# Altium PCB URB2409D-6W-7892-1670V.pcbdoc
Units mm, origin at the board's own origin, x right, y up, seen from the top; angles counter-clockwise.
Board outline 80 x 45 mm, 2 copper layers (Top Layer, Bottom Layer), stack 0.78 mm thick; 36 components, 14 nets, 82 pads, 146 vias.
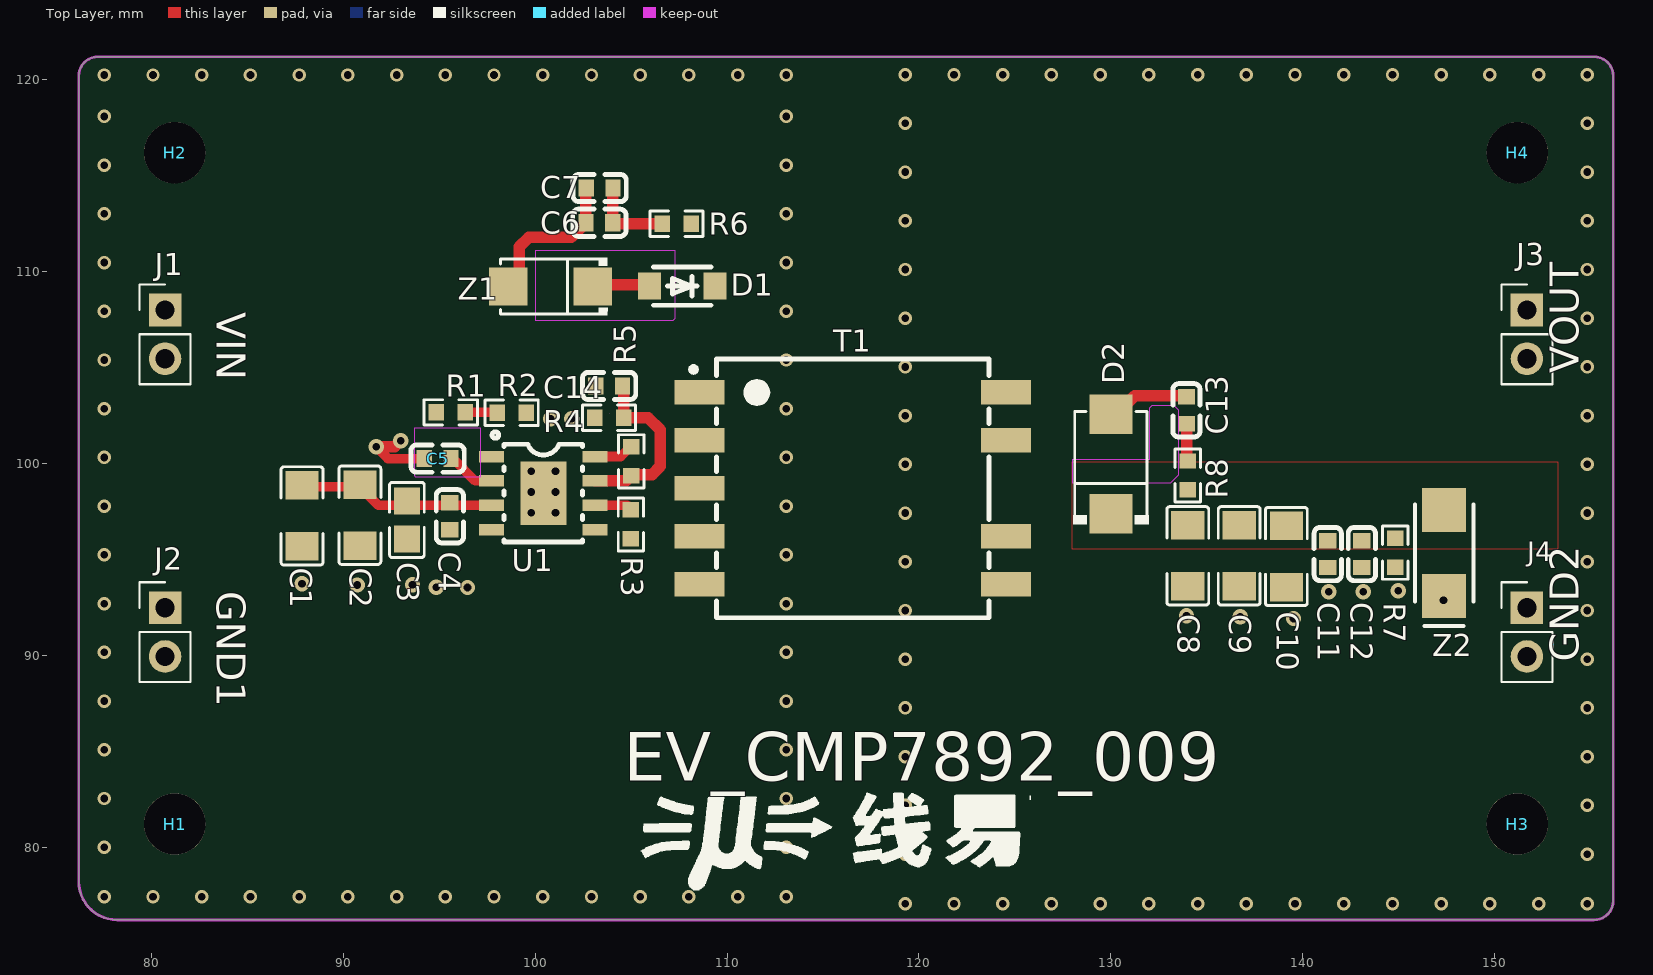
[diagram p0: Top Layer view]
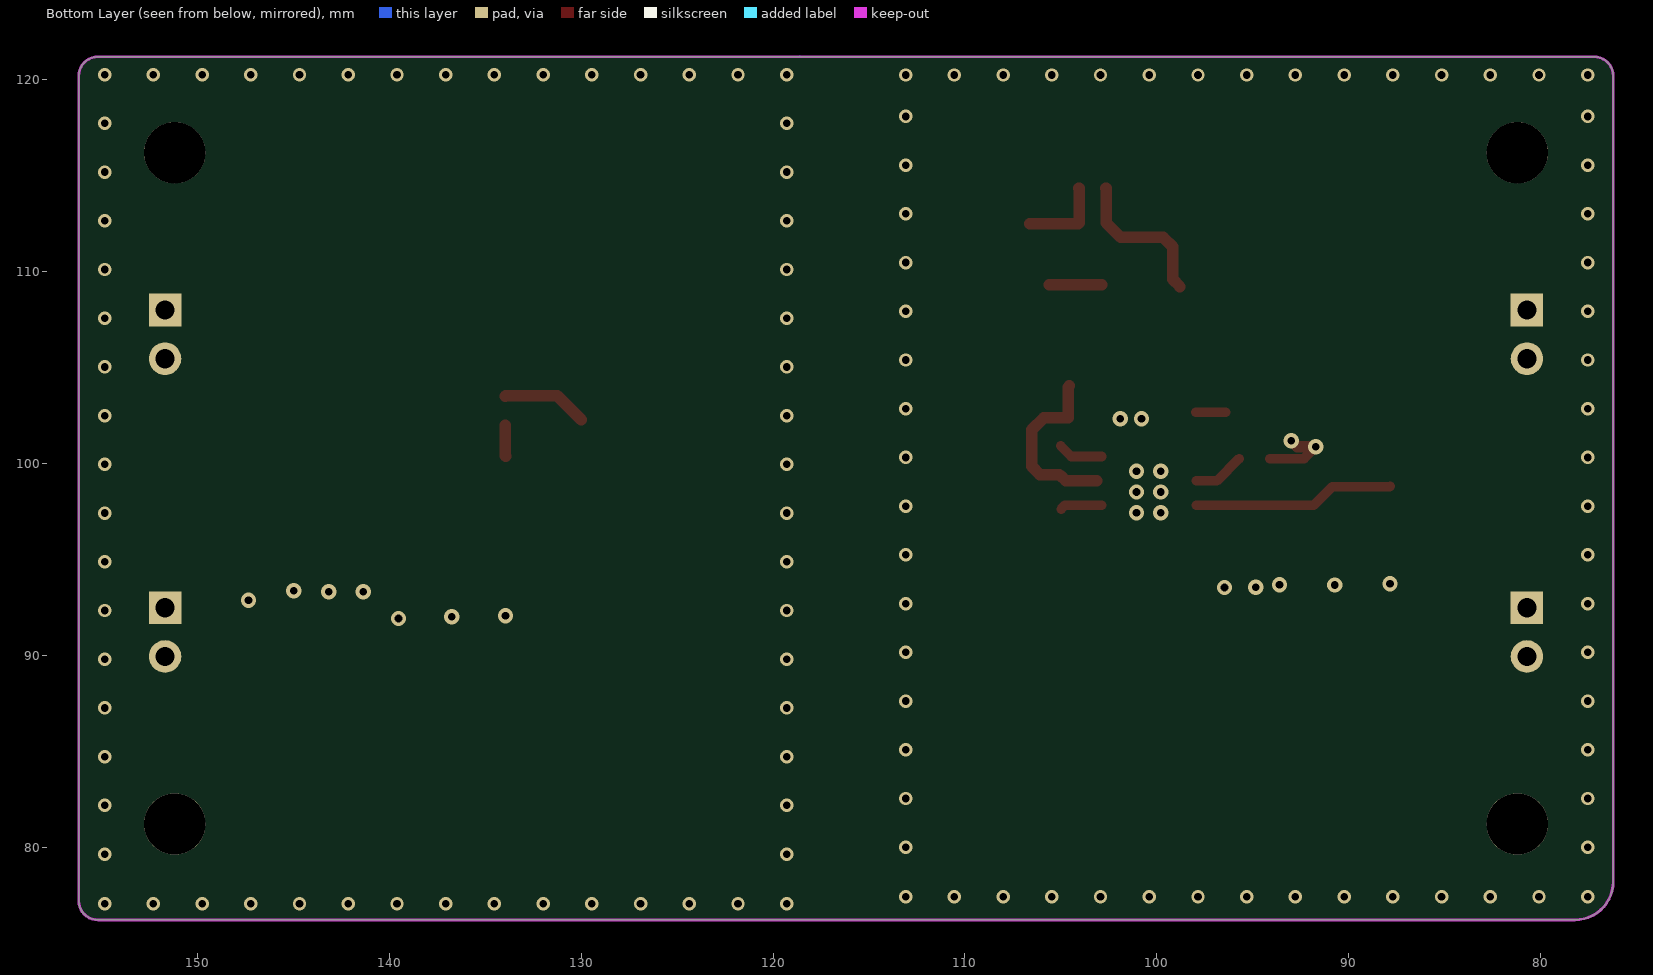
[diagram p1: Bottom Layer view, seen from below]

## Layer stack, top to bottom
Top Solder Mask Layer: solder mask 0.01, Dk 3.3
Top Layer: signal copper 0.035
Dielectric1: surface 0.71, FR4, Dk 4.5
Bottom Layer: signal copper 0.035
Bottom Solder Mask Layer: solder mask 0.01, Dk 3.3

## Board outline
76.2,120.2 cw(c77.2,120.2) 77.2,121.2 155.2,121.2 cw(c155.2,120.2) 156.2,120.2 156.2,77.2 cw(c155.2,77.2) 155.2,76.2 78.2,76.2 cw(c78.2,78.2) 76.2,78.2

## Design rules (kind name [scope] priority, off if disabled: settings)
BoardOutlineClearance safeClearance [All] p0: genericclearance=0.254 ignorepadtopadclearanceinfootprint=FALSE except(0: Arc-SplitContinuation Track-SplitContinuation SMDPad-SplitContinuation THPad-SplitContinuation Via-SplitContinuation Fill-SplitContinuation Poly-SplitContinuation Region-SplitContinuation Text-SplitContinuation)
BoardOutlineClearance Plane_innerPlane [All] p0: genericclearance=0.254 ignorepadtopadclearanceinfootprint=FALSE except(0: Arc-SplitContinuation Track-SplitContinuation SMDPad-SplitContinuation THPad-SplitContinuation Via-SplitContinuation Fill-SplitContinuation Poly-SplitContinuation Region-SplitContinuation Text-SplitContinuation)
BoardOutlineClearance Copper_CopperRegion [All] p0: genericclearance=0.254 ignorepadtopadclearanceinfootprint=FALSE except(0: Arc-SplitContinuation Track-SplitContinuation SMDPad-SplitContinuation THPad-SplitContinuation Via-SplitContinuation Fill-SplitContinuation Poly-SplitContinuation Region-SplitContinuation Text-SplitContinuation)
BoardOutlineClearance Copper_CopperRegion1 [All] p0: genericclearance=0.254 ignorepadtopadclearanceinfootprint=FALSE except(0: Arc-SplitContinuation Track-SplitContinuation SMDPad-SplitContinuation THPad-SplitContinuation Via-SplitContinuation Fill-SplitContinuation Poly-SplitContinuation Region-SplitContinuation Text-SplitContinuation)
BoardOutlineClearance Copper_CopperRegion2 [All] p0: genericclearance=0.254 ignorepadtopadclearanceinfootprint=FALSE except(0: Arc-SplitContinuation Track-SplitContinuation SMDPad-SplitContinuation THPad-SplitContinuation Via-SplitContinuation Fill-SplitContinuation Poly-SplitContinuation Region-SplitContinuation Text-SplitContinuation)
BoardOutlineClearance Copper_CopperRegion3 [All] p0: genericclearance=0.254 ignorepadtopadclearanceinfootprint=FALSE except(0: Arc-SplitContinuation Track-SplitContinuation SMDPad-SplitContinuation THPad-SplitContinuation Via-SplitContinuation Fill-SplitContinuation Poly-SplitContinuation Region-SplitContinuation Text-SplitContinuation)
BoardOutlineClearance Copper_CopperRegion4 [All] p0: genericclearance=0.254 ignorepadtopadclearanceinfootprint=FALSE except(0: Arc-SplitContinuation Track-SplitContinuation SMDPad-SplitContinuation THPad-SplitContinuation Via-SplitContinuation Fill-SplitContinuation Poly-SplitContinuation Region-SplitContinuation Text-SplitContinuation)
BoardOutlineClearance Copper_CopperRegion5 [All] p0: genericclearance=0.254 ignorepadtopadclearanceinfootprint=FALSE except(0: Arc-SplitContinuation Track-SplitContinuation SMDPad-SplitContinuation THPad-SplitContinuation Via-SplitContinuation Fill-SplitContinuation Poly-SplitContinuation Region-SplitContinuation Text-SplitContinuation)
BoardOutlineClearance Copper_CopperRegion6 [All] p0: genericclearance=0.254 ignorepadtopadclearanceinfootprint=FALSE except(0: Arc-SplitContinuation Track-SplitContinuation SMDPad-SplitContinuation THPad-SplitContinuation Via-SplitContinuation Fill-SplitContinuation Poly-SplitContinuation Region-SplitContinuation Text-SplitContinuation)
BoardOutlineClearance Copper_CopperRegion7 [All] p0: genericclearance=0.254 ignorepadtopadclearanceinfootprint=FALSE except(0: Arc-SplitContinuation Track-SplitContinuation SMDPad-SplitContinuation THPad-SplitContinuation Via-SplitContinuation Fill-SplitContinuation Poly-SplitContinuation Region-SplitContinuation Text-SplitContinuation)
BoardOutlineClearance Copper_CopperRegion8 [All] p0: genericclearance=0.254 ignorepadtopadclearanceinfootprint=FALSE except(0: Arc-SplitContinuation Track-SplitContinuation SMDPad-SplitContinuation THPad-SplitContinuation Via-SplitContinuation Fill-SplitContinuation Poly-SplitContinuation Region-SplitContinuation Text-SplitContinuation)
BoardOutlineClearance Copper_CopperRegion9 [All] p0: genericclearance=0.254 ignorepadtopadclearanceinfootprint=FALSE except(0: Arc-SplitContinuation Track-SplitContinuation SMDPad-SplitContinuation THPad-SplitContinuation Via-SplitContinuation Fill-SplitContinuation Poly-SplitContinuation Region-SplitContinuation Text-SplitContinuation)
BoardOutlineClearance Copper_CopperRegion10 [All] p0: genericclearance=0.254 ignorepadtopadclearanceinfootprint=FALSE except(0: Arc-SplitContinuation Track-SplitContinuation SMDPad-SplitContinuation THPad-SplitContinuation Via-SplitContinuation Fill-SplitContinuation Poly-SplitContinuation Region-SplitContinuation Text-SplitContinuation)
BoardOutlineClearance Copper_CopperRegion11 [All] p0: genericclearance=0.254 ignorepadtopadclearanceinfootprint=FALSE except(0: Arc-SplitContinuation Track-SplitContinuation SMDPad-SplitContinuation THPad-SplitContinuation Via-SplitContinuation Fill-SplitContinuation Poly-SplitContinuation Region-SplitContinuation Text-SplitContinuation)
BoardOutlineClearance otherClearance [All] p0: genericclearance=0.254 ignorepadtopadclearanceinfootprint=FALSE except(0: Arc-SplitContinuation Track-SplitContinuation SMDPad-SplitContinuation THPad-SplitContinuation Via-SplitContinuation Fill-SplitContinuation Poly-SplitContinuation Region-SplitContinuation Text-SplitContinuation)
Clearance safeClearance [All] p1: gap=0.178 ignorepadtopadclearanceinfootprint=FALSE
Clearance Plane_innerPlane [All] p1: gap=0.178 ignorepadtopadclearanceinfootprint=FALSE
Clearance Copper_CopperRegion [All] p1: gap=0.178 ignorepadtopadclearanceinfootprint=FALSE
Clearance Copper_CopperRegion1 [All] p1: gap=0.178 ignorepadtopadclearanceinfootprint=FALSE
Clearance Copper_CopperRegion2 [All] p1: gap=0.178 ignorepadtopadclearanceinfootprint=FALSE
Clearance Copper_CopperRegion3 [All] p1: gap=0.178 ignorepadtopadclearanceinfootprint=FALSE
Clearance Copper_CopperRegion4 [All] p1: gap=0.178 ignorepadtopadclearanceinfootprint=FALSE
Clearance Copper_CopperRegion5 [All] p1: gap=0.178 ignorepadtopadclearanceinfootprint=FALSE
Clearance Copper_CopperRegion6 [All] p1: gap=0.178 ignorepadtopadclearanceinfootprint=FALSE
Clearance Copper_CopperRegion7 [All] p1: gap=0.178 ignorepadtopadclearanceinfootprint=FALSE
Clearance Copper_CopperRegion8 [All] p1: gap=0.178 ignorepadtopadclearanceinfootprint=FALSE
Clearance Copper_CopperRegion9 [All] p1: gap=0.178 ignorepadtopadclearanceinfootprint=FALSE
Clearance Copper_CopperRegion10 [All] p1: gap=0.178 ignorepadtopadclearanceinfootprint=FALSE
Clearance Copper_CopperRegion11 [All] p1: gap=0.178 ignorepadtopadclearanceinfootprint=FALSE
Clearance otherClearance [All] p1: gap=0.178 ignorepadtopadclearanceinfootprint=FALSE
DiffPairsRouting differentialPair [All] p1: maxuncoupledlength=10 minlimit=6 maxlimit=Infinity mostfreqgap=6 toplayer_minwidth=5 toplayer_prefwidth=10 toplayer_maxwidth=100 bottomlayer_minwidth=5 bottomlayer_prefwidth=10 bottomlayer_maxwidth=100
PasteMaskExpansion Common [All] p1: expansion=0
PlaneConnect innerPlane [All] p1: planeconnectstyle=Relief reliefexpansion=0.508 reliefentries=4 reliefconductorwidth=0.254 reliefairgap=0.254
PolygonConnect CopperRegion [All] p1: connectstyle=Direct reliefentries=4 reliefconductorwidth=10 polygonreliefangle="90 Angle" airgapwidth=10
PolygonConnect CopperRegion1 [All] p1: connectstyle=Direct reliefentries=4 reliefconductorwidth=10 polygonreliefangle="90 Angle" airgapwidth=10
PolygonConnect CopperRegion2 [All] p1: connectstyle=Direct reliefentries=4 reliefconductorwidth=10 polygonreliefangle="90 Angle" airgapwidth=10
PolygonConnect CopperRegion3 [All] p1: connectstyle=Direct reliefentries=4 reliefconductorwidth=10 polygonreliefangle="90 Angle" airgapwidth=10
PolygonConnect CopperRegion4 [All] p1: connectstyle=Relief reliefentries=4 reliefconductorwidth=0 polygonreliefangle="90 Angle" airgapwidth=1
PolygonConnect CopperRegion5 [All] p1: connectstyle=Relief reliefentries=4 reliefconductorwidth=0 polygonreliefangle="90 Angle" airgapwidth=1
PolygonConnect CopperRegion6 [All] p1: connectstyle=Direct reliefentries=4 reliefconductorwidth=10 polygonreliefangle="90 Angle" airgapwidth=10
PolygonConnect CopperRegion7 [All] p1: connectstyle=Direct reliefentries=4 reliefconductorwidth=10 polygonreliefangle="90 Angle" airgapwidth=10
PolygonConnect CopperRegion8 [All] p1: connectstyle=Direct reliefentries=4 reliefconductorwidth=10 polygonreliefangle="90 Angle" airgapwidth=10
PolygonConnect CopperRegion9 [All] p1: connectstyle=Direct reliefentries=4 reliefconductorwidth=10 polygonreliefangle="90 Angle" airgapwidth=10
PolygonConnect CopperRegion10 [All] p1: connectstyle=Relief reliefentries=4 reliefconductorwidth=0 polygonreliefangle="90 Angle" airgapwidth=1
PolygonConnect CopperRegion11 [All] p1: connectstyle=Relief reliefentries=4 reliefconductorwidth=0 polygonreliefangle="90 Angle" airgapwidth=1
RoutingVias viaSize [All] p1: viastyle="Through Hole" holewidth=12 minholewidth=11.8 maxholewidth=236.2 width=12 minwidth=11.8 maxwidth=236.2
SolderMaskExpansion Common [All] p1: useseparateexpansions=TRUE expansion=0 expansionbottom=0
Width trackWidth [All] p1: maxlimit=100 minlimit=5 preferedwidth=10

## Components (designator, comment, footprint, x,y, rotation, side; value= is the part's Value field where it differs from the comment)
C1 "" C1206 87.841,97.261 r270 top
C2 "" C1206 90.855,97.3 r270 top
C3 "" C0805#1 93.309,97.051 r270 top
C4 "" C0603 95.545,97.24 r90 top
C5 "" C0603 94.905,100.25 r0 top
C6 "" C0603 103.342,112.545 r0 top
C7 "" C0603 103.356,114.357 r0 top
C8 "" C1206 134.02,95.18 r270 top
C9 "" C1206 136.7,95.18 r270 top
C10 "" C1206 139.156,95.146 r90 top
C11 "" C0805#2 141.315,95.273 r90 top
C12 "" C0603 143.093,95.273 r90 top
C13 "" C0603 133.949,102.766 r90 top
C14 "" C0603 103.85,104.036 r0 top
D1 "" SOD-123_L2.8-W1.8-LS3.7-FD 107.66,109.243 r0 top
D2 "" SMB_L4.6-W3.5-LS5.3-RD 130.012,99.972 r90 top
H1 "Mechanical_MountingHole" MountingHole:MountingHole_3.2mm_M3_DIN965 81.2,81.2 r0 top
H2 "" MountingHole:MountingHole_3.2mm_M3_DIN965 81.2,116.2 r0 top
H3 "" MountingHole:MountingHole_3.2mm_M3_DIN965 151.2,81.2 r0 top
H4 "" MountingHole:MountingHole_3.2mm_M3_DIN965 151.2,116.2 r0 top
J1 "" Connector_PinHeader_2.54mm:PinHeader_1x02_P2.54mm_Vertical 80.7,108 r0 top
J2 "" Connector_PinHeader_2.54mm:PinHeader_1x02_P2.54mm_Vertical 80.7,92.475 r0 top
J3 "" Connector_PinHeader_2.54mm:PinHeader_1x02_P2.54mm_Vertical 151.7,108 r0 top
J4 "Connector_Generic_Conn_01x02" Connector_PinHeader_2.54mm:PinHeader_1x02_P2.54mm_Vertical 151.7,92.475 r0 top
R1 "" R0603 95.595,102.658 r0 top
R2 "" R0603 98.77,102.639 r0 top
R3 "" R0603 104.985,96.82 r270 top
R4 "" R0603 103.85,102.385 r180 top
R5 "" MYLibrary:R0603 105.005,100.11 r270 top
R6 "" R1206 107.37,112.49 r180 top
R7 "" R0603 144.833,95.347 r90 top
R8 "" MYLibrary:R0603 134.012,99.371 r90 top
T1 "" XFMR-SMD_CMB1670V 116.55,98.702 r0 top
U1 "" ? 100.421,98.448 r0 top
Z1 "" SMA_L4.3-W2.6-LS5.2-RD 100.787,109.22 r180 top
Z2 "" Diode_SMD:D_SMA 147.383,95.327 r270 top

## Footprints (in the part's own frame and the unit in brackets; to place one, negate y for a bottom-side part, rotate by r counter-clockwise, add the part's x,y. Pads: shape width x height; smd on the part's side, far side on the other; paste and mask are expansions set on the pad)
C0603 [mm]
  rect 0.8x0.9 smd: 1(-0.7,0) 2(0.7,0)
  silkscreen extent -1.39,-0.71 1.39,0.71
C0805#1 [mm]
  rect 1.41x1.35 smd: 1(-1,0) 2(1,0)
  silkscreen extent -1.96,-0.9 1.96,0.9
C0805#2 [mm]
  rect 0.8x0.9 smd: 1(-0.7,0) 2(0.7,0)
  silkscreen extent -1.39,-0.71 1.39,0.71
C1206 [mm]
  rect 1.485x1.728 smd: 1(-1.593,0) 2(1.593,0)
  silkscreen extent -2.56,-1.09 2.56,1.09
Connector_PinHeader_2.54mm:PinHeader_1x02_P2.54mm_Vertical [mm]
  rect 1.7x1.7 hole 1: 1(0,0)
  round 1.7 hole 1: 2(0,-2.54)
  silkscreen extent -1.33,-3.87 1.33,1.33
Diode_SMD:D_SMA [mm]
  rect 2.3x2.3 smd: 1(-2.25,0) 2(2.25,0)
  silkscreen extent -2.54,-1.52 3.81,1.52
MountingHole:MountingHole_3.2mm_M3_DIN965 [mm]
  round 3.2 hole 3.2 unplated: ""(0,0)
MYLibrary:R0603 [mm]
  rect 0.806x0.864 smd: 1(-0.753,0) 2(0.753,0)
  silkscreen extent -1.39,-0.66 1.39,0.66
R0603 [mm]
  rect 0.806x0.864 smd: 1(-0.753,0) 2(0.753,0)
  silkscreen extent -1.39,-0.66 1.39,0.66
R1206 [mm]
  rect 0.806x0.864 smd: 1(-0.753,0) 2(0.753,0)
  silkscreen extent -1.39,-0.66 1.39,0.66
SMA_L4.3-W2.6-LS5.2-RD [mm]
  rect 2x2 smd: 1(-2.2,0) 2(2.2,0)
  silkscreen extent -2.98,-1.5 2.6,1.5
SMB_L4.6-W3.5-LS5.3-RD [mm]
  rect 2.047x2.241 smd: 1(-2.591,0) 2(2.591,0)
  silkscreen extent -3.13,-1.96 2.73,1.96
SOD-123_L2.8-W1.8-LS3.7-FD [mm]
  rect 1.2x1.4 smd: 1(-1.7,0) 2(1.7,0)
  silkscreen extent -1.5,-1 1.5,1
XFMR-SMD_CMB1670V [mm]
  rect 2.62x1.27 smd: 1(-7.99,5) 2(-7.99,2.5) 3(-7.99,0) 4(-7.99,-2.5) 5(-7.99,-5) 6(7.99,-5) 7(7.99,-2.5) 9(7.99,2.5) 10(7.99,5)
  silkscreen extent -8.57,-6.75 7.1,6.75
? [mm]
  rect 1.3x0.6 smd: 1(-2.7,1.905) 2(-2.7,0.635) 3(-2.7,-0.635) 4(-2.7,-1.905) 5(2.7,-1.905) 6(2.7,-0.635) 7(2.7,0.635) 8(2.7,1.905)
  rect 2.4x3.3 smd: 9(0,0)
  silkscreen extent -2.67,-2.55 2.05,3.2

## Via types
v1: diameter 0.7, hole 0.4, Top Layer to Bottom Layer, 124 vias
v2: diameter 0.8, hole 0.4, Top Layer to Bottom Layer, 22 vias

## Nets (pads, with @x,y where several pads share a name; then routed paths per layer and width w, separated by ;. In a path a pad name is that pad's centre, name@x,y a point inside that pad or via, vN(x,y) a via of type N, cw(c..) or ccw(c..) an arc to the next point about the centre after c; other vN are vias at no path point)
$1N7: C13.1 R8.2 | length 1.6
  Top Layer w0.6: R8.2@133.95,100.37 133.97,100.39 C13.1@133.97,101.99
$1N594: D1.1 Z1.1 | length 2.8
  Top Layer w0.25: Z1.1@102.788,109.22 Z1.1@102.878,109.31
  Top Layer w0.6: Z1.1@102.878,109.31 D1.1@105.6,109.31
$1N2001: C5.2 U1.2 | length 2.7
  Top Layer w0.5: C5.2@95.705,100.25 96.865,99.09 U1.2@97.925,99.09
$1N2197: C6.2 C7.2 R6.2 | length 4.3
  Top Layer w0.599: C6.2 104.042,114.344 C7.2
  Top Layer w0.6: C6.2@104.104,112.49 R6.2
$1N9856: C13.2 D2.2 T1.9 T1.10 | length 4.5
  Top Layer w0.599: D2.2@130.003,102.276 131.255,103.528 133.932,103.528 C13.2@133.97,103.49
EN: R1.2 R2.1 | length 1.6
  Top Layer w0.5: R1.2@96.395,102.658 R2.1@97.955,102.658
GND1: C1.2 C2.2 C3.2 C4.1 C5.1 C14.1 J2.1 J2.2 R2.2 R4.2 U1.4 U1.9 | length 4.1
  Top Layer w0.5: v2(91.712,100.861) 92.323,100.25 C5.1@94.105,100.25
  Top Layer w0.599: v2(91.712,100.861) 92.666,100.861 v2(92.985,101.18)
  other v1: 77.53,77.4 80.07,77.4 82.61,77.4 85.15,77.4 87.69,77.4 90.23,77.4 92.77,77.4 95.31,77.4 97.85,77.4 100.39,77.4 102.93,77.4 105.47,77.4 108.01,77.4 110.55,77.4 113.09,77.4 77.53,79.99 113.09,79.99 77.53,82.53 113.09,82.53 77.53,85.07 113.09,85.07 77.53,87.61 113.09,87.61 77.53,90.15 113.09,90.15 77.53,92.69 113.09,92.69 77.53,95.23 113.09,95.23 77.53,97.77 113.09,97.77 77.53,100.31 113.09,100.31 77.53,102.85 113.09,102.85 77.53,105.39 113.09,105.39 77.53,107.93 113.09,107.93 77.53,110.47 113.09,110.47 77.53,113.01 113.09,113.01 77.53,115.55 113.09,115.55 77.53,118.09 113.09,118.09 77.53,120.249 80.07,120.249 82.61,120.249 85.15,120.249 87.69,120.249 90.23,120.249 92.77,120.249 95.31,120.249 97.85,120.249 100.39,120.249 102.93,120.249 105.47,120.249 108.01,120.249 110.55,120.249 113.09,120.249
  other v2: 96.465,93.53 94.835,93.55 90.715,93.66 93.6,93.67 87.835,93.73 99.786,97.432 101.056,97.432 99.786,98.511 101.056,98.511 99.786,99.591 101.056,99.591 100.795,102.32 101.895,102.32
GND2: C8.2 C9.2 C10.1 C11.1 C12.1 J4.1 J4.2 R7.1 T1.6 T1.7 Z2.2
  other v1: 119.29,77.04 121.83,77.04 124.37,77.04 126.91,77.04 129.45,77.04 131.99,77.04 134.53,77.04 137.07,77.04 139.61,77.04 142.15,77.04 144.69,77.04 147.23,77.04 149.77,77.04 152.31,77.04 154.85,77.04 119.29,79.63 154.85,79.63 119.29,82.17 154.85,82.17 119.29,84.71 154.85,84.71 119.29,87.25 154.85,87.25 119.29,89.79 154.85,89.79 119.29,92.33 154.85,92.33 119.29,94.87 154.85,94.87 119.29,97.41 154.85,97.41 119.29,99.95 154.85,99.95 119.29,102.49 154.85,102.49 119.29,105.03 154.85,105.03 119.29,107.57 154.85,107.57 119.29,110.11 154.85,110.11 119.29,112.65 154.85,112.65 119.29,115.19 154.85,115.19 119.29,117.73 154.85,117.73 119.29,120.27 121.83,120.27 124.37,120.27 126.91,120.27 129.45,120.27 131.99,120.27 134.53,120.27 137.07,120.27 139.61,120.27 142.15,120.27 144.69,120.27 147.23,120.27 149.77,120.27 152.31,120.27 154.85,120.27
  other v2: 139.53,91.91 136.75,92 133.95,92.05 147.352,92.86 141.37,93.301 143.175,93.301 144.998,93.368
RFB: R3.1 U1.6 | length 2.2
  Top Layer w0.5: U1.6@102.875,97.82 104.785,97.82 R3.1@104.985,97.62
RREF: C14.2 R4.1 R5.2 U1.7 | length 9.5
  Top Layer w0.599: U1.7 104.731,99.083 R5.2 105.069,99.421 106.093,99.421 106.517,99.845 106.517,101.75 105.882,102.385 R4.1 104.604,103.983 C14.2
SW: D1.2 R3.2 R6.1 T1.3 T1.4 U1.5
TC: R5.1 U1.8 | length 2.4
  Top Layer w0.5: U1.8@102.875,100.36 104.455,100.36 R5.1@105.005,100.91
VIN: C1.1 C2.1 C3.1 C4.2 C6.1 C7.1 J1.1 J1.2 R1.1 T1.1 T1.2 U1.3 Z1.2 | length 18.6
  Top Layer w0.5: C1.1@87.825,98.815 87.865,98.775 90.855,98.775 91.81,97.82 U1.3@97.925,97.82
  Top Layer w0.599: Z1.2@98.787,109.22 99.168,109.601 99.168,111.292 99.659,111.783 101.88,111.783 C6.1 102.642,114.344 C7.1
VOUT: C8.1 C9.1 C10.2 C11.2 C12.2 D2.1 J3.1 J3.2 R7.2 R8.1 Z2.1
pads on no net: H1. H2. H3. H4. T1.5 U1.1

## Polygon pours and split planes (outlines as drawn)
VOUT on Top Layer (solid, remove dead copper, pour order 0): 153.5,109.8 153.5,95.53 128.337,95.4 128.32,98.76 145.464,98.848 148.19,103.09 148.19,109.24 148.75,109.8
GND2 on Bottom Layer (solid, remove dead copper, pour order 18): 118.6,121.2 156.2,121.2 156.2,76.2 118.6,76.2
GND2 on Bottom Layer (solid, remove dead copper, pour order 20): 118.542,121.2 118.6,121.2 118.6,121.258
SW on Top Layer (solid, remove dead copper, pour order 2): 106.87,99.31 109.64,99.31 110.149,99.829 110.149,105.206 107.395,107.96 107.395,112.81 107.955,113.37 110.368,113.37 111.632,112.106 111.632,96.357 110.595,95.32 102.14,95.32 102.14,96.82 106.165,96.82 106.87,97.79
$1N9856 on Top Layer (solid, remove dead copper, pour order 4): 122.31,106.07 131.88,106.07 131.88,100.41 122.31,100.41
GND1 on Top Layer (solid, remove dead copper, pour order 6): 98.941,104.527 103.768,104.527 103.768,101.22 101.895,101.22 101.695,101.02 101.695,100.195 101.505,100.005 101.505,99.28 101.445,99.22 99.695,99.22 99.295,99.62 99.295,99.97 98.941,100.324
GND1 on Top Layer (solid, remove dead copper, pour order 8): 90.985,101.68 93.705,101.68 93.705,100.131 90.985,100.131
VIN on Top Layer (solid, remove dead copper, pour order 10): 78.9,111.01 109.358,111.01 109.358,97.53 78.9,97.53
GND1 on Top Layer (solid, remove dead copper, pour order 12): 76.2,121.2 113.858,121.2 113.858,76.2 76.2,76.2
GND1 on Bottom Layer (solid, remove dead copper, pour order 22): 76.2,121.2 113.858,121.2 113.858,76.2 76.2,76.2
GND2 on Top Layer (solid, remove dead copper, pour order 14): 118.542,121.29 156.2,121.29 156.2,76.2 118.542,76.2
VOUT on Top Layer (solid, remove dead copper, pour order 16): 127.997,100.08 153.32,100.08 153.32,95.53 127.997,95.53

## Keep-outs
Top Layer:
  region: 128.016,98.956 128.016,100.226 132.044,100.226 132.044,102.893 132.171,103.02 133.3,103.02 133.529,102.79 133.529,99.384 133.102,98.956
  region: 103.88,102.59 103.89,102.59 103.89,102.6
  region: 93.755,99.3 97.166,99.3 97.166,101.834 93.685,101.834 93.685,99.37
  region: 100.037,111.1 107.267,111.1 107.267,107.552 107.155,107.44 101.72,107.44 100.037,107.44
Board Outline Layer:
  the board outline again, w0.15

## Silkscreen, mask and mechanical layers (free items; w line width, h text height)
Top Silkscreen Layer:
  drawing of 10 lines, arcs and shapes, not listed
  text "VIN" at 83.403,107.89 h1.5 r270
  text "VOUT" at 154.396,104.707 h1.5 r90
  text "GND1" at 83.403,93.333 h1.5 r270
  text "GND2" at 154.396,89.658 h1.5 r90
  text "EV_CMP7892_009" at 104.612,83.462 h2.54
